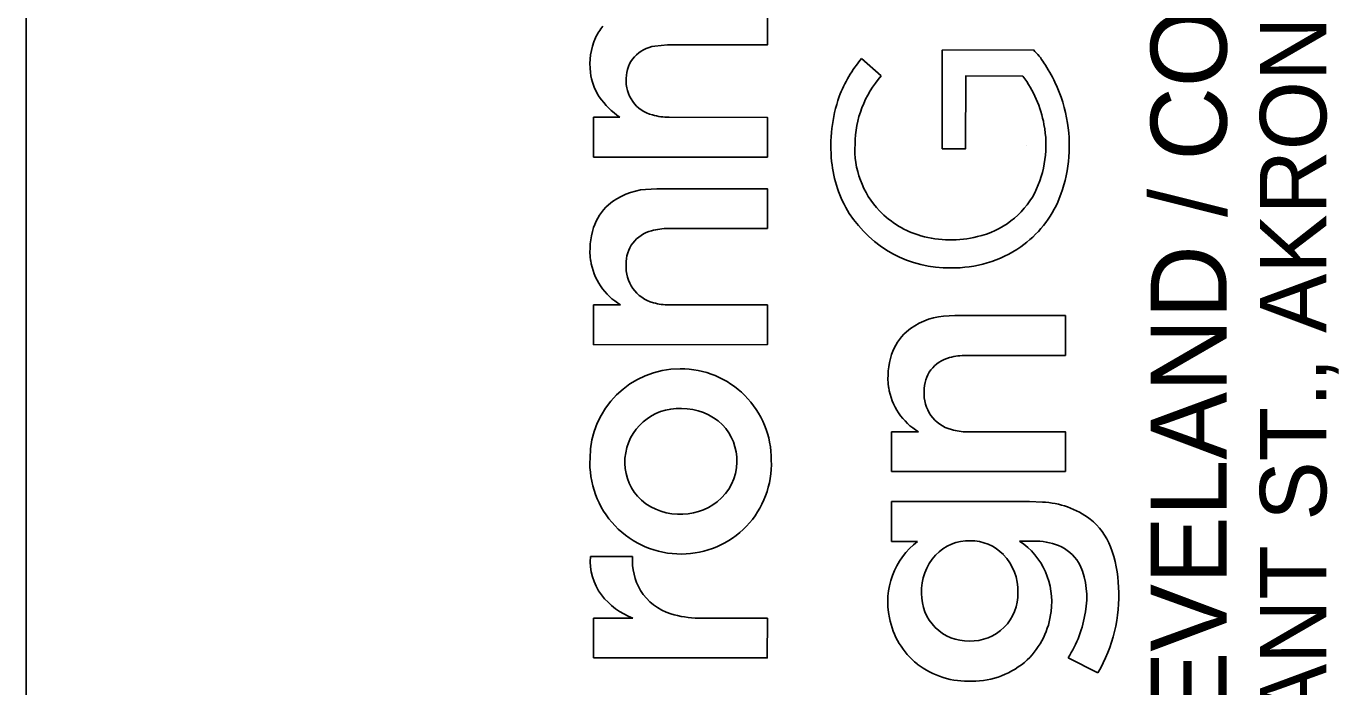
# Model space of a CAD drawing. Extents: x -0.4 to 34, y 0 to 22.
# Drawn here: x 32 to 32.984, y 3.094 to 3.59 of the extents above; entities that cross this region are included whole.
import ezdxf

# ---------------------------------------------------------------- set-up
doc = ezdxf.new("R2010")
doc.units = 0
doc.layers.add('SH_Border', color=7, linetype='Continuous')
doc.layers.add('SH_Cut_Line', color=7, linetype='Continuous')

msp = doc.modelspace()

# ---------------------------------------------------------------- linework, layer by layer
at = {"layer": 'SH_Border'}
for p, q in [((32.55571, 3.60548), (32.55571, 3.57568)), ((32.4809, 3.57567), (32.47143, 3.57474)), ((32.55571, 3.57568), (32.4809, 3.57567)), ((32.62636, 3.56548), (32.64114, 3.55241)), ((32.6868, 3.57185), (32.75516, 3.57192)), ((32.6868, 3.49778), (32.6868, 3.57185)), ((32.70448, 3.55241), (32.70432, 3.49775)), ((32.74737, 3.55227), (32.70448, 3.55241)), ((32.42542, 3.49152), (32.42545, 3.52138)), ((32.42545, 3.52138), (32.44515, 3.52138)), ((32.48206, 3.52138), (32.55571, 3.52136)), ((32.55571, 3.52136), (32.55571, 3.49156)), ((32.70432, 3.49775), (32.6868, 3.49778)), ((32.75, 3.5), (32.75, 3.5)), ((32.55571, 3.49156), (32.42542, 3.49152)), ((32.46439, 3.46736), (32.47289, 3.46783)), ((32.47289, 3.46783), (32.55571, 3.46783)), ((32.55571, 3.46783), (32.55571, 3.43804)), ((32.55571, 3.43804), (32.4814, 3.43796)), ((32.42542, 3.38066), (32.44552, 3.38071)), ((32.42542, 3.35086), (32.42542, 3.38066)), ((32.48222, 3.38071), (32.55569, 3.38071)), ((32.55569, 3.38071), (32.55571, 3.35096)), ((32.68784, 3.3722), (32.69634, 3.37266)), ((32.69634, 3.37266), (32.77916, 3.37266)), ((32.77916, 3.37266), (32.77917, 3.34287)), ((32.55571, 3.35096), (32.42542, 3.35086)), ((32.77917, 3.34287), (32.70485, 3.3428)), ((32.64888, 3.2855), (32.66897, 3.28555)), ((32.64888, 3.25569), (32.64888, 3.2855)), ((32.70568, 3.28555), (32.77915, 3.28555)), ((32.77915, 3.28555), (32.77917, 3.25579)), ((32.77917, 3.25579), (32.64888, 3.25569)), ((32.6489, 3.20336), (32.64889, 3.23322)), ((32.64889, 3.23322), (32.75236, 3.23322)), ((32.75236, 3.23322), (32.76191, 3.23285)), ((32.66836, 3.20336), (32.6489, 3.20336)), ((32.75763, 3.20356), (32.74487, 3.20361)), ((32.42299, 3.19193), (32.45454, 3.19193)), ((32.42542, 3.14577), (32.45473, 3.14579)), ((32.42542, 3.11593), (32.42542, 3.14577)), ((32.50413, 3.14581), (32.55571, 3.14573)), ((32.55571, 3.14573), (32.55565, 3.11593)), ((32.55565, 3.11593), (32.42542, 3.11593)), ((32.8036, 3.10491), (32.7812, 3.11598))]:
    msp.add_line(p, q, dxfattribs=at)
for points in [[(32.48218, 3.60553), (32.55571, 3.60548), (32.55571, 3.57568), (32.4809, 3.57567), (32.47143, 3.57474)], [(32.62636, 3.56548), (32.64114, 3.55241)], [(32.74737, 3.55227), (32.70448, 3.55241), (32.70432, 3.49775), (32.6868, 3.49778), (32.6868, 3.57185), (32.75516, 3.57192)], [(32.42542, 3.49152), (32.42545, 3.52138), (32.44515, 3.52138)], [(32.48206, 3.52138), (32.55571, 3.52136), (32.55571, 3.49156), (32.42542, 3.49152)], [(32.46439, 3.46736), (32.47289, 3.46783), (32.55571, 3.46783), (32.55571, 3.43804), (32.4814, 3.43796)], [(32.42542, 3.35086), (32.42542, 3.38066), (32.44552, 3.38071)], [(32.48222, 3.38071), (32.55569, 3.38071), (32.55571, 3.35096), (32.42542, 3.35086)], [(32.68784, 3.3722), (32.69634, 3.37266), (32.77916, 3.37266), (32.77917, 3.34287), (32.70485, 3.3428)], [(32.64888, 3.25569), (32.64888, 3.2855), (32.66897, 3.28555)], [(32.70568, 3.28555), (32.77915, 3.28555), (32.77917, 3.25579), (32.64888, 3.25569)], [(32.66836, 3.20336), (32.6489, 3.20336), (32.64889, 3.23322), (32.75236, 3.23322), (32.76191, 3.23285)], [(32.75763, 3.20356), (32.74487, 3.20361)], [(32.42299, 3.19193), (32.45454, 3.19193)], [(32.50413, 3.14581), (32.55571, 3.14573), (32.55565, 3.11593), (32.42542, 3.11593)], [(32.42542, 3.11593), (32.42542, 3.14577), (32.45473, 3.14579)], [(32.8036, 3.10491), (32.7812, 3.11598)]]:
    msp.add_lwpolyline(points, dxfattribs=at)
for centre, radius, start, end in [((32.46194, 3.56452), 0.03875, 139.52447, 154.84698), ((32.46194, 3.56452), 0.03875, 139.52447, 154.84698), ((32.47144, 3.5612), 0.04877, 156.06382, 187.3493), ((32.47144, 3.5612), 0.04877, 156.06382, 187.3493), ((32.47421, 3.55056), 0.02434, 96.5532, 179.94902), ((32.47421, 3.55056), 0.02434, 96.5532, 179.94902), ((32.70163, 3.50187), 0.09855, 139.79476, 159.13696), ((32.70163, 3.50187), 0.09855, 139.79476, 159.13696), ((32.72498, 3.53937), 0.04438, 30.98913, 47.16099), ((32.72498, 3.53937), 0.04438, 30.98913, 47.16099), ((32.46461, 3.55974), 0.04181, 186.5579, 213.38846), ((32.46461, 3.55974), 0.04181, 186.5579, 213.38846), ((32.67091, 3.50018), 0.11106, 25.30315, 33.96179), ((32.67091, 3.50018), 0.11106, 25.30315, 33.96179), ((32.47608, 3.54863), 0.02628, 175.722, 255.78627), ((32.47608, 3.54863), 0.02628, 175.722, 255.78627), ((32.69899, 3.50079), 0.07753, 138.25804, 179.70064), ((32.69899, 3.50079), 0.07753, 138.25804, 179.70064), ((32.67889, 3.50099), 0.08556, 10.07509, 36.83189), ((32.67889, 3.50099), 0.08556, 10.07509, 36.83189), ((32.6704, 3.49987), 0.11166, 8.80339, 25.33484), ((32.6704, 3.49987), 0.11166, 8.80339, 25.33484), ((32.47886, 3.57078), 0.0598, 214.70433, 235.68724), ((32.47886, 3.57078), 0.0598, 214.70433, 235.68724), ((32.7187, 3.49968), 0.11536, 161.14379, 185.62812), ((32.7187, 3.49968), 0.11536, 161.14379, 185.62812), ((32.48195, 3.56518), 0.0438, 253.66719, 270.14979), ((32.48195, 3.56518), 0.0438, 253.66719, 270.14979), ((32.68425, 3.50057), 0.08036, 333.46689, 11.03668), ((32.68425, 3.50057), 0.08036, 333.46689, 11.03668), ((32.67564, 3.49977), 0.10649, 338.28866, 9.28548), ((32.67564, 3.49977), 0.10649, 338.28866, 9.28548), ((32.68811, 3.49732), 0.06676, 176.66577, 223.6912), ((32.68811, 3.49732), 0.06676, 176.66577, 223.6912), ((32.69336, 3.49699), 0.08987, 185.50773, 212.01294), ((32.69336, 3.49699), 0.08987, 185.50773, 212.01294), ((32.46871, 3.41767), 0.04988, 94.97056, 130.22484), ((32.46871, 3.41767), 0.04988, 94.97056, 130.22484), ((32.69868, 3.49547), 0.0652, 282.88151, 331.81475), ((32.69868, 3.49547), 0.0652, 282.88151, 331.81475), ((32.46348, 3.42602), 0.04016, 132.22383, 161.68229), ((32.46348, 3.42602), 0.04016, 132.22383, 161.68229), ((32.69835, 3.49168), 0.08241, 305.03061, 337.67573), ((32.69835, 3.49168), 0.08241, 305.03061, 337.67573), ((32.69211, 3.49748), 0.08908, 212.70222, 270.71399), ((32.69211, 3.49748), 0.08908, 212.70222, 270.71399), ((32.69045, 3.50011), 0.07039, 224.02147, 253.88), ((32.69045, 3.50011), 0.07039, 224.02147, 253.88), ((32.47872, 3.42158), 0.05602, 162.27398, 187.79173), ((32.47872, 3.42158), 0.05602, 162.27398, 187.79173), ((32.47482, 3.41206), 0.02498, 103.68683, 182.21395), ((32.47482, 3.41206), 0.02498, 103.68683, 182.21395), ((32.48108, 3.39196), 0.04601, 89.60515, 105.33026), ((32.48108, 3.39196), 0.04601, 89.60515, 105.33026), ((32.69318, 3.51254), 0.08309, 254.45353, 283.9512), ((32.69318, 3.51254), 0.08309, 254.45353, 283.9512), ((32.69429, 3.49979), 0.09138, 269.3273, 304.19632), ((32.69429, 3.49979), 0.09138, 269.3273, 304.19632), ((32.47027, 3.42141), 0.04763, 188.96462, 238.69865), ((32.47027, 3.42141), 0.04763, 188.96462, 238.69865), ((32.47735, 3.40897), 0.02757, 175.58441, 255.13816), ((32.47735, 3.40897), 0.02757, 175.58441, 255.13816), ((32.48183, 3.42286), 0.04215, 254.08913, 270.52838), ((32.48183, 3.42286), 0.04215, 254.08913, 270.52838), ((32.69216, 3.32251), 0.04988, 94.97056, 130.22484), ((32.69216, 3.32251), 0.04988, 94.97056, 130.22484), ((32.68694, 3.33085), 0.04016, 132.22383, 161.68229), ((32.68694, 3.33085), 0.04016, 132.22383, 161.68229), ((32.70217, 3.32642), 0.05602, 162.27398, 187.79173), ((32.70217, 3.32642), 0.05602, 162.27398, 187.79173), ((32.69828, 3.31689), 0.02498, 103.68683, 182.21395), ((32.69828, 3.31689), 0.02498, 103.68683, 182.21395), ((32.70453, 3.29679), 0.04601, 89.60515, 105.33026), ((32.70453, 3.29679), 0.04601, 89.60515, 105.33026), ((32.49014, 3.26543), 0.0674, 89.84756, 179.64047), ((32.49014, 3.26543), 0.0674, 89.84756, 179.64047), ((32.49057, 3.26474), 0.0681, 359.54009, 90.21138), ((32.49057, 3.26474), 0.0681, 359.54009, 90.21138), ((32.69372, 3.32624), 0.04763, 188.96462, 238.69865), ((32.69372, 3.32624), 0.04763, 188.96462, 238.69865), ((32.7008, 3.31381), 0.02757, 175.58441, 255.13816), ((32.7008, 3.31381), 0.02757, 175.58441, 255.13816), ((32.48923, 3.26263), 0.0404, 87.04809, 175.57259), ((32.48923, 3.26263), 0.0404, 87.04809, 175.57259), ((32.49204, 3.25999), 0.04299, 45.84264, 90.98008), ((32.49204, 3.25999), 0.04299, 45.84264, 90.98008), ((32.49458, 3.26421), 0.03821, 357.88569, 44.15902), ((32.49458, 3.26421), 0.03821, 357.88569, 44.15902), ((32.70529, 3.32769), 0.04215, 254.08913, 270.52838), ((32.70529, 3.32769), 0.04215, 254.08913, 270.52838), ((32.49083, 3.26209), 0.06819, 176.8344, 270.40384), ((32.49083, 3.26209), 0.06819, 176.8344, 270.40384), ((32.48729, 3.2625), 0.03848, 175.15378, 221.14706), ((32.48729, 3.2625), 0.03848, 175.15378, 221.14706), ((32.49123, 3.26139), 0.06749, 270.06243, 2.37759), ((32.49123, 3.26139), 0.06749, 270.06243, 2.37759), ((32.49446, 3.26318), 0.0383, 308.28936, 359.43468), ((32.49446, 3.26318), 0.0383, 308.28936, 359.43468), ((32.48919, 3.26607), 0.04228, 223.09994, 268.80895), ((32.48919, 3.26607), 0.04228, 223.09994, 268.80895), ((32.49096, 3.2679), 0.04418, 266.56515, 308.06078), ((32.49096, 3.2679), 0.04418, 266.56515, 308.06078), ((32.75907, 3.16789), 0.06503, 53.40344, 87.49062), ((32.75907, 3.16789), 0.06503, 53.40344, 87.49062), ((32.76517, 3.18039), 0.05141, 21.60748, 50.5577), ((32.76517, 3.18039), 0.05141, 21.60748, 50.5577), ((32.70292, 3.15813), 0.05692, 127.37482, 192.22468), ((32.70292, 3.15813), 0.05692, 127.37482, 192.22468), ((32.70693, 3.16927), 0.0346, 88.47302, 136.42562), ((32.70693, 3.16927), 0.0346, 88.47302, 136.42562), ((32.70814, 3.16963), 0.03424, 44.27195, 90.47623), ((32.70814, 3.16963), 0.03424, 44.27195, 90.47623), ((32.71421, 3.15829), 0.05472, 352.1125, 55.92295), ((32.71421, 3.15829), 0.05472, 352.1125, 55.92295), ((32.75666, 3.15725), 0.04633, 65.01687, 88.8011), ((32.75666, 3.15725), 0.04633, 65.01687, 88.8011), ((32.7626, 3.17155), 0.03085, 26.26808, 63.80301), ((32.7626, 3.17155), 0.03085, 26.26808, 63.80301), ((32.73069, 3.16714), 0.08835, 1.15143, 21.3627), ((32.73069, 3.16714), 0.08835, 1.15143, 21.3627), ((32.46616, 3.18882), 0.04329, 175.87313, 216.34747), ((32.46616, 3.18882), 0.04329, 175.87313, 216.34747), ((32.50087, 3.18948), 0.04639, 176.9688, 209.60636), ((32.50087, 3.18948), 0.04639, 176.9688, 209.60636), ((32.71141, 3.16602), 0.0401, 137.46739, 182.33237), ((32.71141, 3.16602), 0.0401, 137.46739, 182.33237), ((32.70368, 3.166), 0.03996, 358.57141, 43.53765), ((32.70368, 3.166), 0.03996, 358.57141, 43.53765), ((32.73565, 3.16154), 0.05953, 349.30734, 23.43071), ((32.73565, 3.16154), 0.05953, 349.30734, 23.43071), ((32.47466, 3.19716), 0.05511, 218.09809, 248.7907), ((32.47466, 3.19716), 0.05511, 218.09809, 248.7907), ((32.49514, 3.18814), 0.04079, 211.94466, 253.2028), ((32.49514, 3.18814), 0.04079, 211.94466, 253.2028), ((32.70645, 3.1637), 0.03511, 178.88208, 271.08374), ((32.70645, 3.1637), 0.03511, 178.88208, 271.08374), ((32.70818, 3.16404), 0.03546, 268.27882, 1.55016), ((32.70818, 3.16404), 0.03546, 268.27882, 1.55016), ((32.70538, 3.16244), 0.11383, 329.6388, 3.25998), ((32.70538, 3.16244), 0.11383, 329.6388, 3.25998), ((32.70988, 3.15708), 0.05887, 313.74196, 353.8554), ((32.70988, 3.15708), 0.05887, 313.74196, 353.8554), ((32.70738, 3.16334), 0.08771, 327.31495, 351.57478), ((32.70738, 3.16334), 0.08771, 327.31495, 351.57478), ((32.50465, 3.2165), 0.07069, 252.46555, 269.57296), ((32.50465, 3.2165), 0.07069, 252.46555, 269.57296), ((32.70463, 3.15696), 0.05837, 190.75182, 231.28919), ((32.70463, 3.15696), 0.05837, 190.75182, 231.28919), ((32.70632, 3.16112), 0.06269, 232.46061, 272.59022), ((32.70632, 3.16112), 0.06269, 232.46061, 272.59022), ((32.70954, 3.15901), 0.06051, 269.6361, 312.70877), ((32.70954, 3.15901), 0.06051, 269.6361, 312.70877)]:
    msp.add_arc(centre, radius, start, end, dxfattribs=at)
at = {"layer": 'SH_Cut_Line'}
msp.add_line((32, 0.5), (32, 21.5), dxfattribs=at)

# ---------------------------------------------------------------- texts
at = {"layer": 'SH_Border'}
for s, height, p in [('450 GRANT ST., AKRON, OH  44311', 0.0498462, (32.97489, 2.83738)), ('AKRON / CLEVELAND / COLUMBUS', 0.056969, (32.90012, 2.638))]:
    msp.add_text(s, height=height, rotation=90, dxfattribs=at).set_placement(p)

doc.saveas('drawing.dxf')
